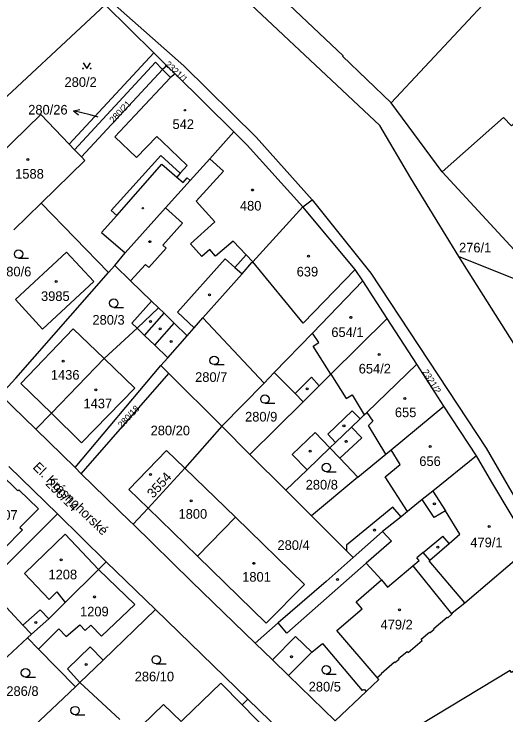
# Model space of a CAD drawing. Extents: x -679220 to -673243, y -1075091 to -1066557.
# Drawn here: x -676104.3 to -676017.5, y -1072146.6 to -1072022.8 of the extents above; entities that cross this region are included whole.
import ezdxf

# ---------------------------------------------------------------- set-up
doc = ezdxf.new("R2010")
doc.units = 0
for name, color, linetype in [('Hranice parcel', 7, 'Continuous'), ('Parcelní čísla', 7, 'Continuous'), ('Pop  PČ popisy', 7, 'Continuous'), ('Vnitřní kresba', 7, 'Continuous'), ('Značky budov', 7, 'Continuous'), ('Značky kultur', 7, 'Continuous')]:
    doc.layers.add(name, color=color, linetype=linetype)

msp = doc.modelspace()

# ---------------------------------------------------------------- linework, layer by layer
at = {"layer": 'Hranice parcel'}
for p, q in [((-676088.2, -1072021.23), (-676079.63, -1072029.69)), ((-676094.56, -1072045.83), (-676079.63, -1072029.69)), ((-676079.63, -1072029.69), (-676077.31, -1072031.98)), ((-676078.1, -1072032.62), (-676092.43, -1072048.05)), ((-676077.31, -1072031.98), (-676078.1, -1072032.62)), ((-676028.71, -1072050.67), (-676037.74, -1072038.5)), ((-676093.64, -1072046.79), (-676094.56, -1072045.83)), ((-676092.43, -1072048.05), (-676093.64, -1072046.79)), ((-676028.71, -1072050.67), (-676016.02, -1072064.44)), ((-676099.5, -1072056.21), (-676104.37, -1072060.94)), ((-676099.5, -1072056.21), (-676087.63, -1072068.46)), ((-676053.31, -1072056.85), (-676051.66, -1072055.61)), ((-676087.63, -1072068.46), (-676086.54, -1072067.22)), ((-676038.41, -1072076.58), (-676042.73, -1072069.92)), ((-676070.96, -1072076.48), (-676060.16, -1072087.97)), ((-676033.17, -1072084.65), (-676038.41, -1072076.58)), ((-676097.71, -1072093.31), (-676088.38, -1072083.66)), ((-676093.54, -1072102.88), (-676078.37, -1072084.88)), ((-676078.37, -1072084.88), (-676076.96, -1072086.29)), ((-676028.42, -1072092.05), (-676033.17, -1072084.65)), ((-676092.46, -1072103.98), (-676076.96, -1072086.29)), ((-676076.96, -1072086.29), (-676067.64, -1072095.61)), ((-676060.16, -1072087.97), (-676058.36, -1072086.12)), ((-676067.64, -1072095.61), (-676060.16, -1072087.97)), ((-676106.71, -1072090.05), (-676100.47, -1072096.13)), ((-676053.28, -1072091.29), (-676062.66, -1072100.6)), ((-676022.66, -1072100.85), (-676028.42, -1072092.05)), ((-676097.71, -1072093.31), (-676100.47, -1072096.13)), ((-676100.47, -1072096.13), (-676093.54, -1072102.88)), ((-676067.64, -1072095.61), (-676074.17, -1072103)), ((-676062.66, -1072100.6), (-676067.64, -1072095.61)), ((-676062.66, -1072100.6), (-676056.33, -1072106.9)), ((-676096.63, -1072111.09), (-676105.25, -1072102.7)), ((-676093.54, -1072102.88), (-676092.46, -1072103.98)), ((-676074.17, -1072103), (-676080.66, -1072110.07)), ((-676065.23, -1072111.67), (-676074.17, -1072103)), ((-676043.59, -1072104.59), (-676051.82, -1072111.39)), ((-676051.82, -1072111.39), (-676056.33, -1072106.9)), ((-676088.04, -1072119.52), (-676096.63, -1072111.09)), ((-676080.66, -1072110.07), (-676083.25, -1072112.89)), ((-676080.66, -1072110.07), (-676071.92, -1072118.56)), ((-676071.92, -1072118.56), (-676065.23, -1072111.67)), ((-676039.23, -1072114.17), (-676044.43, -1072118.76)), ((-676079.34, -1072127.98), (-676088.04, -1072119.52)), ((-676063.03, -1072143.78), (-676079.34, -1072127.98)), ((-676110.52, -1072140.89), (-676101.95, -1072132.98)), ((-676101.25, -1072132.29), (-676101.95, -1072132.98)), ((-676055.85, -1072139.6), (-676047.63, -1072147.58)), ((-676102.62, -1072150.19), (-676093.48, -1072141.61)), ((-676093.48, -1072141.61), (-676092.68, -1072140.85)), ((-676092.68, -1072140.85), (-676085.63, -1072147.39)), ((-676042.12, -1072142.42), (-676047.63, -1072147.58))]:
    msp.add_line(p, q, dxfattribs=at)
for points in [[(-676025.75, -1072065.64), (-676034.25, -1072051.8), (-676039.72, -1072042.53), (-676096.55, -1071989.19), (-676094.44, -1071985.56)], [(-676092.58, -1071986.74), (-676084.09, -1071994.75), (-676083.99, -1071994.64), (-676073.48, -1072004.6), (-676074.16, -1072005.33), (-676057.51, -1072020.9), (-676056.82, -1072020.17), (-676046.21, -1072030.2), (-676046.31, -1072030.3), (-676037.74, -1072038.5)], [(-676037.74, -1072038.5), (-676019.92, -1072019.42), (-676018.32, -1072017.74), (-676018.23, -1072017.83), (-676014.59, -1072014.01), (-676014.67, -1072013.92), (-676013.15, -1072012.32)], [(-676092.13, -1072017.41), (-676091.46, -1072016.8), (-676074.31, -1072031.96), (-676061.55, -1072044.59), (-676051.66, -1072055.61)], [(-675988.29, -1072016.27), (-675993.45, -1072021.14), (-675997.34, -1072024.81), (-676000.8, -1072028.07), (-676009.28, -1072035.69), (-676009.2, -1072035.78), (-676016.47, -1072042.6), (-676017.87, -1072041.11), (-676028.71, -1072050.67)], [(-676132.12, -1072062.03), (-676122.54, -1072053.13), (-676111.1, -1072042.44), (-676109.89, -1072041.36), (-676088.2, -1072021.23)], [(-676078.1, -1072032.62), (-676079.32, -1072031.36), (-676093.64, -1072046.79)], [(-676065.48, -1072043.64), (-676075.86, -1072033.42), (-676077.31, -1072031.98)], [(-676094.56, -1072045.83), (-676099.6, -1072040.58), (-676112.26, -1072052.87)], [(-676086.54, -1072067.22), (-676084.68, -1072064.98), (-676077.55, -1072057.06), (-676073.19, -1072052.21), (-676069.75, -1072048.38), (-676065.48, -1072043.64)], [(-676065.48, -1072043.64), (-676063.14, -1072046.01), (-676053.31, -1072056.85)], [(-676092.43, -1072048.05), (-676091.79, -1072048.71), (-676099.5, -1072056.21)], [(-676051.66, -1072055.61), (-676041.29, -1072068.57), (-676020.94, -1072099.46), (-676011.5, -1072115.85)], [(-676070.96, -1072076.48), (-676064.06, -1072068.7), (-676062.32, -1072066.72), (-676062.16, -1072066.56), (-676053.31, -1072056.85)], [(-676042.73, -1072069.92), (-676044.06, -1072067.96), (-676053.31, -1072056.85)], [(-676095.03, -1072064.85), (-676090.21, -1072070.04), (-676099.28, -1072078.47), (-676104.08, -1072073.22), (-676095.03, -1072064.85)], [(-676012.81, -1072086.13), (-676014.27, -1072083.86), (-676025.75, -1072065.64)], [(-676025.75, -1072065.64), (-676012.93, -1072070.74), (-675990.95, -1072074.52)], [(-676086.54, -1072067.22), (-676083.73, -1072069.95), (-676080.06, -1072073.51), (-676078.79, -1072074.73)], [(-676106.71, -1072090.05), (-676104.02, -1072087.14), (-676087.63, -1072068.46)], [(-676058.36, -1072086.12), (-676051.59, -1072079.17), (-676042.73, -1072069.92)], [(-676078.79, -1072074.73), (-676082.6, -1072078.28), (-676088.38, -1072083.66)], [(-676078.79, -1072074.73), (-676077.83, -1072075.67), (-676076.04, -1072077.4), (-676073.74, -1072079.63)], [(-676073.74, -1072079.63), (-676072.48, -1072078.21), (-676070.96, -1072076.48)], [(-676053.28, -1072091.29), (-676050.42, -1072088.45), (-676048.35, -1072086.43), (-676038.41, -1072076.58)], [(-676088.38, -1072083.66), (-676093.85, -1072078.42), (-676103.1, -1072088.04), (-676097.71, -1072093.31)], [(-676078.37, -1072084.88), (-676077.18, -1072083.53), (-676073.74, -1072079.63)], [(-676048.54, -1072099.42), (-676047.55, -1072098.46), (-676044.74, -1072095.76), (-676043.22, -1072094.3), (-676042.5, -1072093.61), (-676042.04, -1072093.17), (-676033.17, -1072084.65)], [(-676058.36, -1072086.12), (-676054.7, -1072089.85), (-676053.28, -1072091.29)], [(-676043.59, -1072104.59), (-676038.66, -1072100.52), (-676037.73, -1072099.75), (-676028.42, -1072092.05)], [(-676074.17, -1072103), (-676077.38, -1072099.89), (-676084.06, -1072106.77), (-676080.66, -1072110.07)], [(-676056.33, -1072106.9), (-676052.58, -1072103.3), (-676048.54, -1072099.42)], [(-676048.54, -1072099.42), (-676046.78, -1072101.26), (-676043.59, -1072104.59)], [(-676022.66, -1072100.85), (-676030.36, -1072107.08), (-676032.25, -1072108.52), (-676034.83, -1072110.68), (-676035.97, -1072111.58), (-676039.23, -1072114.17)], [(-676013.15, -1072116.89), (-676019.98, -1072105.48), (-676022.66, -1072100.85)], [(-676083.25, -1072112.89), (-676083.78, -1072112.42), (-676092.46, -1072103.98)], [(-676109.37, -1072123.64), (-676106.83, -1072121.16), (-676096.63, -1072111.09)], [(-676071.92, -1072118.56), (-676059.78, -1072130.34), (-676053.03, -1072123.54), (-676065.23, -1072111.67)], [(-676051.82, -1072111.39), (-676045.59, -1072117.6), (-676044.43, -1072118.76)], [(-676083.25, -1072112.89), (-676072.98, -1072122.98), (-676061.71, -1072133.91)], [(-676039.23, -1072114.17), (-676037.64, -1072115.91), (-676042.15, -1072119.75), (-676039.44, -1072122.74), (-676038.39, -1072123.98), (-676033.93, -1072120.27), (-676027.08, -1072128.72)], [(-676027.08, -1072128.72), (-676026.9, -1072128.59), (-676026.97, -1072128.51), (-676024.74, -1072126.76), (-676013.15, -1072116.89)], [(-676101.25, -1072132.29), (-676098.15, -1072129.57), (-676095.28, -1072126.73), (-676089.39, -1072120.91), (-676088.04, -1072119.52)], [(-676044.43, -1072118.76), (-676049.19, -1072123.03), (-676057.66, -1072130.28), (-676061.71, -1072133.91)], [(-676109.37, -1072123.64), (-676102.74, -1072130.71), (-676101.25, -1072132.29)], [(-676092.68, -1072140.85), (-676088.59, -1072136.9), (-676079.34, -1072127.98)], [(-676042.12, -1072142.42), (-676039.88, -1072140.32), (-676040.2, -1072139.94), (-676039.45, -1072139.31), (-676039.52, -1072139.22), (-676037.13, -1072137.21), (-676037.06, -1072137.3), (-676036.34, -1072136.7), (-676036.42, -1072136.61), (-676034.92, -1072135.35), (-676034.75, -1072135.55), (-676032.23, -1072133.43), (-676032.42, -1072133.21), (-676030.93, -1072131.95), (-676030.86, -1072132.03), (-676030.12, -1072131.41), (-676030.19, -1072131.33), (-676027.81, -1072129.33), (-676027.74, -1072129.41), (-676027.01, -1072128.8), (-676027.08, -1072128.72)], [(-676101.95, -1072132.98), (-676100.02, -1072134.94), (-676093.48, -1072141.61)], [(-676061.71, -1072133.91), (-676058.7, -1072136.83), (-676055.85, -1072139.6)], [(-676055.85, -1072139.6), (-676051.74, -1072135.47), (-676049.84, -1072133.98), (-676042.82, -1072142.23), (-676042.68, -1072142.05), (-676042.56, -1072142.19), (-676042.44, -1072142.08), (-676042.12, -1072142.42)], [(-676008.59, -1072134.94), (-676010.58, -1072135.65), (-676016.49, -1072139.09), (-676016.72, -1072138.71), (-676032.8, -1072148.4), (-676032.57, -1072148.78), (-676038.37, -1072152.3), (-676046.51, -1072160.26)], [(-676063.03, -1072143.78), (-676064.04, -1072144.78), (-676067.78, -1072140.98), (-676074.4, -1072147.33), (-676074.82, -1072147.74), (-676077.92, -1072144.7), (-676081.67, -1072148.38), (-676083.12, -1072149.8)], [(-676055.23, -1072153.53), (-676055.21, -1072151.35), (-676063.03, -1072143.78)]]:
    msp.add_lwpolyline(points, dxfattribs=at)
at = {"layer": 'Pop  PČ popisy'}
for p, q in [((-676093.8, -1072039.93), (-676092.71, -1072039.69)), ((-676090.89, -1072040.66), (-676093.8, -1072039.93)), ((-676093.8, -1072039.93), (-676092.95, -1072040.66)), ((-676089.48, -1072041.02), (-676090.89, -1072040.66))]:
    msp.add_line(p, q, dxfattribs=at)
at = {"layer": 'Vnitřní kresba'}
for p, q in [((-676078.1, -1072032.62), (-676076.7, -1072034.06)), ((-676076.7, -1072034.06), (-676082.97, -1072040.76)), ((-676075.86, -1072033.42), (-676076.7, -1072034.06)), ((-676082.97, -1072040.76), (-676086.51, -1072044.49)), ((-676086.51, -1072044.49), (-676082.68, -1072048.15)), ((-676082.68, -1072048.15), (-676079.08, -1072044.47)), ((-676079.08, -1072044.47), (-676078.15, -1072045.36)), ((-676078.15, -1072045.36), (-676073.75, -1072049.55)), ((-676078.42, -1072047.8), (-676087.15, -1072057.53)), ((-676074.98, -1072050.93), (-676078.42, -1072047.8)), ((-676067.33, -1072050.56), (-676069.75, -1072048.38)), ((-676086.18, -1072058.38), (-676078.19, -1072049.35)), ((-676078.19, -1072049.35), (-676075.59, -1072051.61)), ((-676073.75, -1072049.55), (-676074.98, -1072050.93)), ((-676074.98, -1072050.93), (-676075.59, -1072051.61)), ((-676075.59, -1072051.61), (-676074.46, -1072052.6)), ((-676072.18, -1072055.85), (-676067.33, -1072050.56)), ((-676074.46, -1072052.6), (-676073.77, -1072051.76)), ((-676073.77, -1072051.76), (-676073.19, -1072052.21)), ((-676068.84, -1072059.51), (-676072.18, -1072055.85)), ((-676087.15, -1072057.53), (-676086.18, -1072058.38)), ((-676074.56, -1072059.75), (-676077.55, -1072057.06)), ((-676088.87, -1072061.42), (-676086.18, -1072058.38)), ((-676078.05, -1072063.63), (-676074.56, -1072059.75)), ((-676073.16, -1072063.39), (-676068.84, -1072059.51)), ((-676088.87, -1072061.42), (-676084.68, -1072064.98)), ((-676077.45, -1072064.17), (-676078.05, -1072063.63)), ((-676071.14, -1072065.63), (-676073.16, -1072063.39)), ((-676065.65, -1072062.91), (-676068.72, -1072065.6)), ((-676063.31, -1072065.35), (-676065.65, -1072062.91)), ((-676080.53, -1072067.59), (-676077.45, -1072064.17)), ((-676069.76, -1072064.42), (-676071.14, -1072065.63)), ((-676068.72, -1072065.6), (-676069.76, -1072064.42)), ((-676067.02, -1072066.07), (-676075.46, -1072075.44)), ((-676065.3, -1072067.6), (-676067.02, -1072066.07)), ((-676063.31, -1072065.35), (-676065.3, -1072067.6)), ((-676062.16, -1072066.56), (-676063.31, -1072065.35)), ((-676053.24, -1072077.38), (-676062.16, -1072066.56)), ((-676083.73, -1072069.95), (-676081.12, -1072067.05)), ((-676081.12, -1072067.05), (-676080.53, -1072067.59)), ((-676065.3, -1072067.6), (-676064.06, -1072068.7)), ((-676044.06, -1072067.96), (-676053.24, -1072077.38)), ((-676080.06, -1072073.51), (-676083.5, -1072077.41)), ((-676081.27, -1072079.57), (-676077.83, -1072075.67)), ((-676075.46, -1072075.44), (-676072.48, -1072078.21)), ((-676083.5, -1072077.41), (-676082.6, -1072078.28)), ((-676079.48, -1072081.3), (-676076.04, -1072077.4)), ((-676082.6, -1072078.28), (-676081.27, -1072079.57)), ((-676081.27, -1072079.57), (-676079.48, -1072081.3)), ((-676050.5, -1072080.82), (-676051.59, -1072079.17)), ((-676079.48, -1072081.3), (-676077.18, -1072083.53)), ((-676051.51, -1072081.49), (-676050.5, -1072080.82)), ((-676048.35, -1072086.43), (-676051.51, -1072081.49)), ((-676082.96, -1072088.87), (-676088.38, -1072083.66)), ((-676054.7, -1072089.85), (-676051.8, -1072086.95)), ((-676051.8, -1072086.95), (-676050.42, -1072088.45)), ((-676048.35, -1072086.43), (-676045.65, -1072090.71)), ((-676092.39, -1072098.52), (-676082.96, -1072088.87)), ((-676045.65, -1072090.71), (-676044.63, -1072090.07)), ((-676044.63, -1072090.07), (-676042.5, -1072093.61)), ((-676097.71, -1072093.31), (-676092.39, -1072098.52)), ((-676048.93, -1072097.02), (-676044.61, -1072092.86)), ((-676044.61, -1072092.86), (-676043.22, -1072094.3)), ((-676042.04, -1072093.17), (-676040.99, -1072094.72)), ((-676041.73, -1072095.46), (-676040.99, -1072094.72)), ((-676044.74, -1072095.76), (-676042.88, -1072097.62)), ((-676038.66, -1072100.52), (-676041.73, -1072095.46)), ((-676055.18, -1072100.59), (-676051.14, -1072096.72)), ((-676051.14, -1072096.72), (-676048.54, -1072099.42)), ((-676047.55, -1072098.46), (-676048.93, -1072097.02)), ((-676042.88, -1072097.62), (-676046.78, -1072101.26)), ((-676036.14, -1072102.37), (-676037.73, -1072099.75)), ((-676052.58, -1072103.3), (-676055.18, -1072100.59)), ((-676038.76, -1072104.54), (-676036.14, -1072102.37)), ((-676106.7, -1072104.03), (-676103.66, -1072107.03)), ((-676034.83, -1072110.68), (-676038.76, -1072104.54)), ((-676103.66, -1072107.03), (-676103.44, -1072106.81)), ((-676103.44, -1072106.81), (-676100.02, -1072110.19)), ((-676030.36, -1072107.08), (-676028.16, -1072110.52)), ((-676030.11, -1072111.69), (-676032.25, -1072108.52)), ((-676100.02, -1072110.19), (-676103.28, -1072113.45)), ((-676037.41, -1072109.9), (-676045.59, -1072116.61)), ((-676035.97, -1072111.58), (-676037.41, -1072109.9)), ((-676028.16, -1072110.52), (-676030.11, -1072111.69)), ((-676025.62, -1072114.65), (-676028.16, -1072110.52)), ((-676103.28, -1072113.45), (-676102.84, -1072113.87)), ((-676102.84, -1072113.87), (-676106.03, -1072117.2)), ((-676095.27, -1072114.68), (-676102.49, -1072121.61)), ((-676089.39, -1072120.91), (-676095.27, -1072114.68)), ((-676027.48, -1072116.32), (-676025.62, -1072114.65)), ((-676032.05, -1072117.91), (-676028.62, -1072114.99)), ((-676027.48, -1072116.32), (-676028.62, -1072114.99)), ((-676045.59, -1072116.61), (-676045.59, -1072117.6)), ((-676030.91, -1072119.24), (-676027.48, -1072116.32)), ((-676032.05, -1072117.91), (-676033.2, -1072118.83)), ((-676030.91, -1072119.24), (-676032.05, -1072117.91)), ((-676042.15, -1072119.75), (-676056.12, -1072132.1)), ((-676033.93, -1072120.27), (-676032.79, -1072119.31)), ((-676032.79, -1072119.31), (-676033.2, -1072118.83)), ((-676031.04, -1072119.35), (-676030.91, -1072119.24)), ((-676024.74, -1072126.76), (-676031.04, -1072119.35)), ((-676082.98, -1072127.07), (-676089.39, -1072120.91)), ((-676102.49, -1072121.61), (-676098.11, -1072126.17)), ((-676043.9, -1072126.57), (-676039.44, -1072122.74)), ((-676098.11, -1072126.17), (-676096.75, -1072124.86)), ((-676096.75, -1072124.86), (-676095.28, -1072126.73)), ((-676088.86, -1072132.68), (-676082.98, -1072127.07)), ((-676042.83, -1072127.82), (-676043.9, -1072126.57)), ((-676099.68, -1072128.02), (-676102.74, -1072130.71)), ((-676098.15, -1072129.57), (-676099.68, -1072128.02)), ((-676047.32, -1072131.65), (-676042.83, -1072127.82)), ((-676095.1, -1072132.7), (-676092.7, -1072130.68)), ((-676092.7, -1072130.68), (-676091.77, -1072131.66)), ((-676091.77, -1072131.66), (-676090.76, -1072130.69)), ((-676090.76, -1072130.69), (-676088.86, -1072132.68)), ((-676056.12, -1072132.1), (-676057.66, -1072130.28)), ((-676100.02, -1072134.94), (-676096.4, -1072131.38)), ((-676096.4, -1072131.38), (-676095.1, -1072132.7)), ((-676040.2, -1072139.94), (-676047.32, -1072131.65)), ((-676058.7, -1072136.83), (-676054.63, -1072132.71)), ((-676054.63, -1072132.71), (-676051.74, -1072135.47)), ((-676090.85, -1072134.55), (-676094.86, -1072138.43)), ((-676088.59, -1072136.9), (-676090.85, -1072134.55)), ((-676094.86, -1072138.43), (-676092.68, -1072140.85)), ((-676064.04, -1072144.78), (-676058.03, -1072150.89))]:
    msp.add_line(p, q, dxfattribs=at)
at = {"layer": 'Značky budov'}
for centre, radius in [((-676074.13, -1072039.83), 0.117), ((-676101.88, -1072048.51), 0.175), ((-676062.19, -1072053.9), 0.175), ((-676081.57, -1072057.12), 0.117), ((-676080.33, -1072063.02), 0.175), ((-676052.34, -1072065.59), 0.175), ((-676096.87, -1072070.04), 0.175), ((-676069.82, -1072072.39), 0.175), ((-676044.87, -1072076.38), 0.175), ((-676080.21, -1072077.09), 0.175), ((-676078.51, -1072078.43), 0.175), ((-676076.57, -1072080.64), 0.175), ((-676039.85, -1072082.94), 0.175), ((-676095.66, -1072084.13), 0.175), ((-676052.54, -1072088.99), 0.175), ((-676089.85, -1072089.17), 0.175), ((-676035.3, -1072090.72), 0.175), ((-676046.06, -1072095.55), 0.175), ((-676045.66, -1072098.27), 0.175), ((-676052.05, -1072099.98), 0.175), ((-676030.83, -1072099.19), 0.175), ((-676080.2, -1072104.13), 0.175), ((-676073.03, -1072108.75), 0.175), ((-676030.1, -1072109.29), 0.175), ((-676020.42, -1072113.31), 0.175), ((-676040.68, -1072113.92), 0.175), ((-676029.49, -1072116.97), 0.175), ((-676095.98, -1072119.2), 0.175), ((-676061.98, -1072119.8), 0.175), ((-676047.19, -1072122.66), 0.175), ((-676090.09, -1072125.74), 0.175), ((-676036.24, -1072128), 0.175), ((-676100.48, -1072130.24), 0.175), ((-676055.33, -1072136.28), 0.175), ((-676091.59, -1072137.64), 0.175)]:
    msp.add_circle(centre, radius, dxfattribs=at)
at = {"layer": 'Značky kultur'}
for p, q in [((-676103.51, -1072065.95), (-676101.76, -1072065.95)), ((-676086.71, -1072074.62), (-676084.96, -1072074.62)), ((-676068.97, -1072084.73), (-676067.22, -1072084.73)), ((-676060.01, -1072091.55), (-676058.26, -1072091.55)), ((-676049.16, -1072103.64), (-676047.41, -1072103.64)), ((-676079.19, -1072137.56), (-676077.44, -1072137.56)), ((-676049.18, -1072139.34), (-676047.43, -1072139.34)), ((-676102.28, -1072139.88), (-676100.53, -1072139.88)), ((-676093.54, -1072146.55), (-676091.79, -1072146.55))]:
    msp.add_line(p, q, dxfattribs=at)
msp.add_lwpolyline([(-676092.13, -1072031.43), (-676091.46, -1072032.44), (-676090.79, -1072031.43)], dxfattribs=at)
for centre, radius in [((-676092.13, -1072032.44), 0.067), ((-676090.79, -1072032.44), 0.067), ((-676103.51, -1072065.2), 0.75), ((-676086.71, -1072073.87), 0.75), ((-676068.97, -1072083.98), 0.75), ((-676060.01, -1072090.8), 0.75), ((-676049.16, -1072102.89), 0.75), ((-676079.19, -1072136.81), 0.75), ((-676049.18, -1072138.59), 0.75), ((-676102.28, -1072139.13), 0.75), ((-676093.54, -1072145.8), 0.75)]:
    msp.add_circle(centre, radius, dxfattribs=at)

# ---------------------------------------------------------------- texts
at = {"layer": 'Parcelní čísla'}
for s, height, rotation, p in [('2321/1', 1.14, 317, (-676077.73, -1072031.86)), ('280/21', 1.14, 47, (-676086.76, -1072042.17)), ('2321/2', 1.14, 302, (-676032.27, -1072086)), ('280/18', 1.14, 47, (-676085.26, -1072095.98)), ('3554', 1.7, 48, (-676079.75, -1072108.41)), ('290/14', 1.7, 315, (-676098.87, -1072105.88))]:
    msp.add_text(s, height=height, rotation=rotation, dxfattribs=at).set_placement(p)
for s, p in [('280/2', (-676095.4, -1072035.7)), ('280/26', (-676101.81, -1072040.58)), ('542', (-676076.33, -1072043.13)), ('1588', (-676104.11, -1072051.9)), ('480', (-676064.43, -1072057.53)), ('276/1', (-676025.74, -1072064.92)), ('280/6', (-676106.95, -1072069.15)), ('639', (-676054.41, -1072069.16)), ('3985', (-676099.55, -1072073.49)), ('280/3', (-676090.47, -1072077.67)), ('654/1', (-676048.29, -1072079.85)), ('654/2', (-676043.46, -1072086.29)), ('1436', (-676097.81, -1072087.38)), ('280/7', (-676072.34, -1072087.77)), ('1437', (-676092.05, -1072092.43)), ('655', (-676037.07, -1072094)), ('280/9', (-676063.52, -1072094.77)), ('280/20', (-676080.2, -1072097.2)), ('656', (-676032.76, -1072102.62)), ('280/8', (-676052.82, -1072106.77)), ('1207', (-676108.73, -1072112.11)), ('1800', (-676075.27, -1072111.93)), ('280/4', (-676057.8, -1072117.43)), ('479/1', (-676023.75, -1072116.96)), ('1208', (-676098.23, -1072122.62)), ('1801', (-676064.03, -1072123.04)), ('1209', (-676092.66, -1072129.16)), ('479/2', (-676039.6, -1072131.46)), ('286/10', (-676083.01, -1072140.63)), ('280/5', (-676052.29, -1072142.42)), ('286/8', (-676105.67, -1072143.2))]:
    msp.add_text(s, height=1.7, dxfattribs=at).set_placement(p)
at = {"layer": 'Pop  PČ popisy'}
msp.add_text('El. Krásnohorské', height=1.7, rotation=316, dxfattribs=at).set_placement((-676101.12, -1072102.97))

doc.saveas('drawing.dxf')
